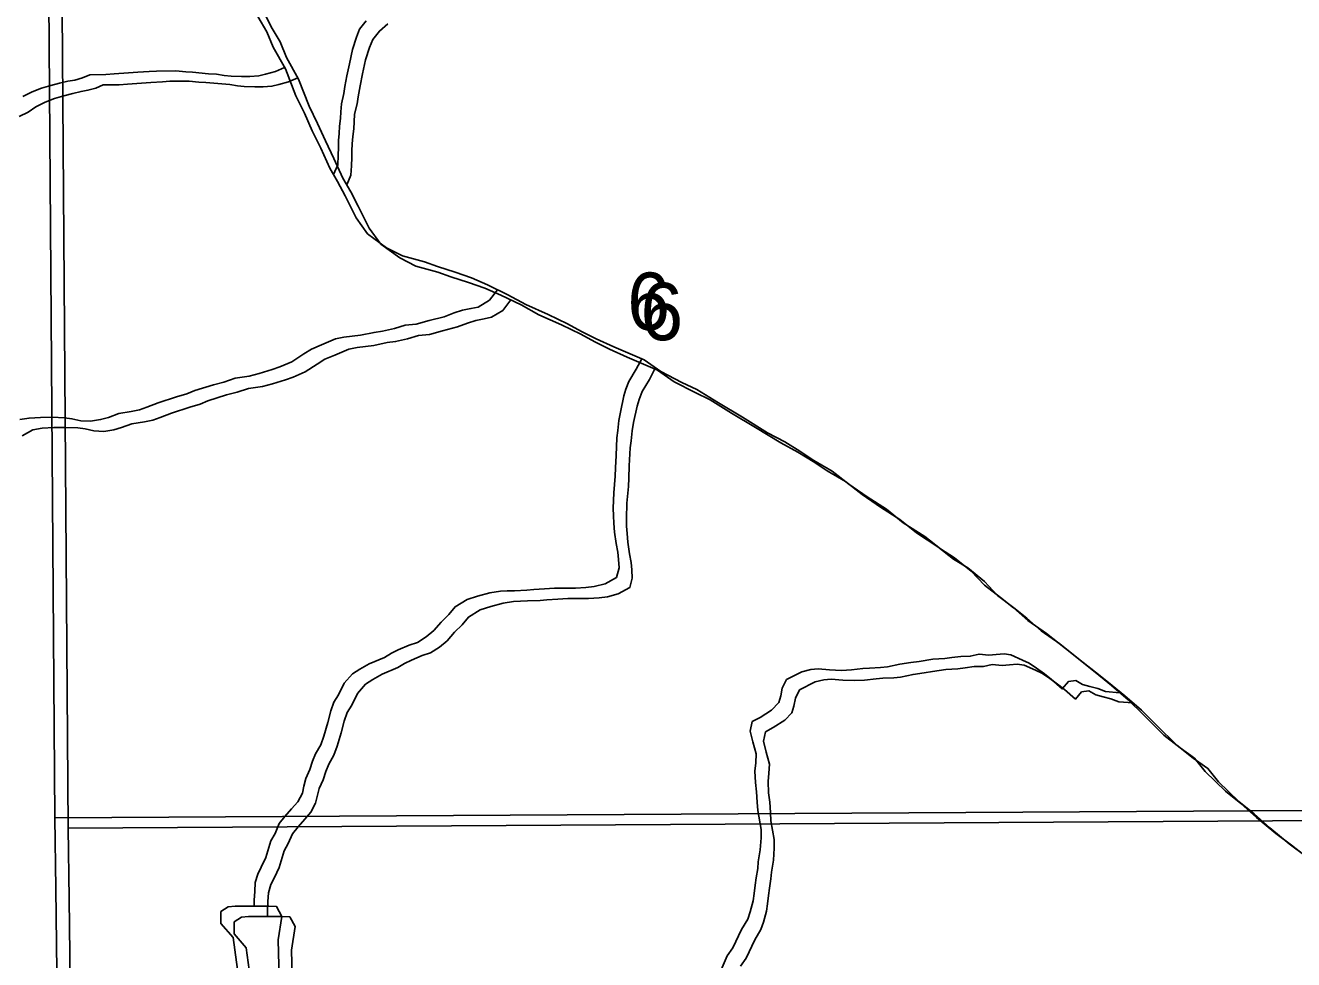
# Model space of a CAD drawing. Extents: x -21.1 to 50.3, y 0 to 22.1.
# Drawn here: x 44.072 to 44.997, y 18.617 to 19.298 of the extents above; entities that cross this region are included whole.
import ezdxf

# ---------------------------------------------------------------- set-up
doc = ezdxf.new("R2010")
doc.units = 0
for name, color, linetype in [('GM_X_Major_River', 7, 'Continuous'), ('GM_X_Minor_Lake', 7, 'Continuous'), ('GM_X_Minor_River', 7, 'Continuous'), ('GM_X_Section', 7, 'Continuous'), ('GM_X_Section_Text', 7, 'Continuous')]:
    doc.layers.add(name, color=color, linetype=linetype)

msp = doc.modelspace()

# ---------------------------------------------------------------- linework, layer by layer
at = {"layer": 'GM_X_Major_River'}
for points in [[(44.24162, 19.30473), (44.24815, 19.29377), (44.25278, 19.28242), (44.26162, 19.26654), (44.26934, 19.24685), (44.27549, 19.23437), (44.28128, 19.22151), (44.28744, 19.20865), (44.29398, 19.19427), (44.29974, 19.18444), (44.30513, 19.17385), (44.3132, 19.15797), (44.32163, 19.14626), (44.33535, 19.13611), (44.34716, 19.13012), (44.36312, 19.12569), (44.37262, 19.12234), (44.38555, 19.11826), (44.39733, 19.11417), (44.40913, 19.10894), (44.42397, 19.10184), (44.43691, 19.09472), (44.45327, 19.08725), (44.46735, 19.08052), (44.47763, 19.0749), (44.48829, 19.06966), (44.50123, 19.06369), (44.52329, 19.05436), (44.53549, 19.04572), (44.55071, 19.03786), (44.56175, 19.03262), (44.57737, 19.02287), (44.59489, 19.01237), (44.61317, 19.00112), (44.62573, 18.99437), (44.63678, 18.98762), (44.64707, 18.98086), (44.6604, 18.97299), (44.6726, 18.96359), (44.68594, 18.9542), (44.70004, 18.94519), (44.71224, 18.93541), (44.72787, 18.92527), (44.73931, 18.91625), (44.74959, 18.90987), (44.7618, 18.90009), (44.77135, 18.88991), (44.78317, 18.88089), (44.7927, 18.87337), (44.80301, 18.86395), (44.81673, 18.85456), (44.83046, 18.84365), (44.84267, 18.83387), (44.8522, 18.82635), (44.86403, 18.81657), (44.87624, 18.80603), (44.88731, 18.7951), (44.90217, 18.78045)], [(44.24625, 19.30782), (44.25126, 19.29723), (44.25779, 19.28627), (44.26242, 19.27492), (44.27125, 19.25904), (44.27898, 19.23935), (44.28513, 19.22687), (44.29091, 19.21401), (44.29707, 19.20114), (44.30362, 19.18677), (44.30938, 19.17694), (44.31476, 19.16635), (44.32284, 19.15047), (44.33127, 19.13876), (44.34499, 19.12861), (44.35679, 19.12262), (44.37275, 19.11819), (44.38226, 19.11484), (44.39518, 19.11076), (44.40697, 19.10667), (44.41876, 19.10144), (44.4336, 19.09434), (44.44655, 19.08722), (44.46291, 19.07975), (44.47699, 19.07302), (44.48727, 19.0674), (44.49793, 19.06216), (44.51086, 19.05619), (44.53293, 19.04686), (44.54512, 19.03822), (44.56035, 19.03036), (44.57139, 19.02512), (44.587, 19.01537), (44.60453, 19.00487), (44.62281, 18.99361), (44.63537, 18.98687), (44.64642, 18.98012), (44.65671, 18.97336), (44.67003, 18.96549), (44.68224, 18.95609), (44.69558, 18.9467), (44.70968, 18.93769), (44.72188, 18.92791), (44.7375, 18.91777), (44.74894, 18.90875), (44.75923, 18.90237), (44.77143, 18.89259), (44.78099, 18.88241), (44.79281, 18.87339), (44.80234, 18.86586), (44.81265, 18.85645), (44.82637, 18.84706), (44.8401, 18.83615), (44.8523, 18.82637), (44.86184, 18.81885), (44.87367, 18.80907), (44.88588, 18.79853), (44.89695, 18.7876), (44.91181, 18.77295)], [(44.90217, 18.78045), (44.91401, 18.77106), (44.92469, 18.76355), (44.93236, 18.75375), (44.94728, 18.73945), (44.95835, 18.73043), (44.96981, 18.72028), (44.98395, 18.70863), (44.9954, 18.69999), (45.00648, 18.69135)], [(44.91181, 18.77295), (44.92364, 18.76356), (44.93433, 18.75605), (44.942, 18.74625), (44.95691, 18.73195), (44.96799, 18.72293), (44.97945, 18.71278), (44.99359, 18.70113), (45.00504, 18.69249)]]:
    msp.add_lwpolyline(points, dxfattribs=at)
at = {"layer": 'GM_X_Minor_Lake'}
for points in [[(44.21461, 18.65156), (44.21467, 18.64283), (44.22347, 18.63265), (44.22789, 18.60043), (44.2322, 18.58186), (44.23497, 18.56556), (44.24714, 18.56224), (44.26028, 18.57943), (44.25707, 18.60294), (44.25649, 18.63102), (44.25901, 18.64812), (44.25517, 18.6553), (44.24947, 18.65564)], [(44.24947, 18.65564), (44.23471, 18.65552), (44.2251, 18.65552), (44.22001, 18.65515), (44.21461, 18.65156)], [(44.22425, 18.64406), (44.22431, 18.63533), (44.23311, 18.62515), (44.23752, 18.59293), (44.24183, 18.57436), (44.24461, 18.55806), (44.25677, 18.55474), (44.26992, 18.57193), (44.26671, 18.59544), (44.26612, 18.62352), (44.26865, 18.64062), (44.2648, 18.6478), (44.25911, 18.64814)], [(44.25911, 18.64814), (44.24435, 18.64802), (44.23474, 18.64802), (44.22965, 18.64764), (44.22425, 18.64406)]]:
    msp.add_lwpolyline(points, dxfattribs=at)
at = {"layer": 'GM_X_Minor_River'}
for points in [[(44.29672, 19.18961), (44.2998, 19.19656), (44.30012, 19.20341), (44.30045, 19.20949), (44.3004, 19.21444), (44.30074, 19.21938), (44.30108, 19.22471), (44.30179, 19.23042), (44.30213, 19.23536), (44.30246, 19.24107), (44.3043, 19.24869), (44.30502, 19.25364), (44.30647, 19.26163), (44.3083, 19.2704), (44.31049, 19.28068), (44.31345, 19.28983), (44.31569, 19.29555), (44.32058, 19.30167)], [(44.30635, 19.18211), (44.30943, 19.18906), (44.30975, 19.19591), (44.31008, 19.20199), (44.31004, 19.20693), (44.31038, 19.21188), (44.31071, 19.21721), (44.31143, 19.22292), (44.31176, 19.22786), (44.3121, 19.23357), (44.31393, 19.24119), (44.31465, 19.24614), (44.3161, 19.25413), (44.31793, 19.26289), (44.32013, 19.27318), (44.32309, 19.28233), (44.32532, 19.28805), (44.33021, 19.29417), (44.33625, 19.29955)], [(44.26099, 19.26767), (44.25435, 19.26463), (44.24714, 19.26267), (44.24221, 19.26149), (44.23575, 19.26106), (44.22967, 19.26101), (44.22206, 19.26133), (44.21711, 19.26167), (44.2114, 19.26276), (44.20569, 19.2631), (44.1939, 19.26414), (44.18895, 19.26448), (44.18172, 19.26518), (44.16765, 19.26507), (44.16233, 19.26465), (44.15397, 19.2642), (44.14713, 19.26376), (44.13687, 19.26292), (44.13079, 19.26249), (44.11901, 19.26239), (44.1137, 19.26007), (44.10801, 19.2585), (44.10308, 19.2577), (44.097, 19.25613), (44.09056, 19.25455), (44.08373, 19.2526), (44.0769, 19.24988), (44.07009, 19.2464)], [(44.27062, 19.26017), (44.26399, 19.25713), (44.25678, 19.25517), (44.25185, 19.25399), (44.24539, 19.25356), (44.2393, 19.25351), (44.2317, 19.25383), (44.22675, 19.25417), (44.22103, 19.25526), (44.21533, 19.2556), (44.20353, 19.25664), (44.19859, 19.25698), (44.19136, 19.25768), (44.17729, 19.25757), (44.17197, 19.25714), (44.16361, 19.2567), (44.15677, 19.25626), (44.14651, 19.25542), (44.14043, 19.25499), (44.12864, 19.25489), (44.12334, 19.25257), (44.11765, 19.251), (44.11271, 19.2502), (44.10664, 19.24863), (44.10019, 19.24705), (44.09336, 19.2451), (44.08654, 19.24238), (44.07973, 19.2389), (44.07406, 19.23505), (44.06762, 19.23196)], [(44.41636, 19.10548), (44.41052, 19.09784), (44.4022, 19.09283), (44.39688, 19.09164), (44.39081, 19.09045), (44.38474, 19.0885), (44.37754, 19.08578), (44.36654, 19.08303), (44.35706, 19.08029), (44.34908, 19.07947), (44.34111, 19.07712), (44.33238, 19.07515), (44.32631, 19.07434), (44.31644, 19.07236), (44.30428, 19.07073), (44.29821, 19.06955), (44.28798, 19.06528), (44.28078, 19.06218), (44.27511, 19.05871), (44.26641, 19.05294), (44.2577, 19.04906), (44.25201, 19.04712), (44.24253, 19.04438), (44.23532, 19.04242), (44.22507, 19.04081), (44.21673, 19.03808), (44.20914, 19.03612), (44.19549, 19.03183), (44.1898, 19.0295), (44.18222, 19.02716), (44.16895, 19.02287), (44.1606, 19.01976), (44.1553, 19.01781), (44.14922, 19.01662), (44.14011, 19.01502), (44.13253, 19.0123), (44.12684, 19.01073), (44.11963, 19.00953), (44.1124, 19.00986), (44.10592, 19.01132), (44.10059, 19.01204), (44.09147, 19.01235), (44.0831, 19.01228), (44.07474, 19.01183), (44.06791, 19.01063)], [(44.426, 19.09798), (44.42016, 19.09033), (44.41183, 19.08532), (44.40652, 19.08414), (44.40045, 19.08295), (44.39438, 19.081), (44.38718, 19.07828), (44.37618, 19.07553), (44.36669, 19.07279), (44.35871, 19.07196), (44.35075, 19.06962), (44.34202, 19.06765), (44.33594, 19.06684), (44.32607, 19.06486), (44.31392, 19.06323), (44.30785, 19.06204), (44.29762, 19.05778), (44.29042, 19.05468), (44.28474, 19.05121), (44.27605, 19.04544), (44.26734, 19.04156), (44.26165, 19.03961), (44.25217, 19.03688), (44.24496, 19.03492), (44.2347, 19.03331), (44.22636, 19.03058), (44.21877, 19.02862), (44.20512, 19.02432), (44.19944, 19.022), (44.19185, 19.01965), (44.17858, 19.01536), (44.17024, 19.01225), (44.16493, 19.01031), (44.15886, 19.00912), (44.14975, 19.00752), (44.14217, 19.0048), (44.13648, 19.00323), (44.12926, 19.00203), (44.12204, 19.00236), (44.11556, 19.00382), (44.11023, 19.00454), (44.1011, 19.00485), (44.09274, 19.00478), (44.08438, 19.00433), (44.07754, 19.00313), (44.06959, 18.99889)], [(44.52148, 19.05512), (44.51741, 19.04737), (44.51216, 19.03859), (44.50993, 19.03286), (44.50845, 19.02791), (44.50589, 19.0161), (44.5048, 19.01001), (44.5041, 19.00278), (44.50339, 18.99745), (44.50274, 18.98451), (44.50243, 18.97539), (44.5021, 18.9693), (44.50107, 18.95712), (44.50078, 18.94609), (44.50083, 18.94039), (44.50125, 18.93507), (44.50169, 18.92861), (44.5029, 18.92025), (44.5041, 18.9138), (44.50452, 18.90848), (44.50495, 18.9024), (44.50311, 18.89554), (44.49478, 18.89091), (44.48681, 18.88894), (44.48074, 18.88813), (44.47314, 18.88769), (44.45793, 18.88757), (44.45071, 18.88713), (44.44273, 18.88668), (44.43779, 18.88626), (44.42867, 18.88581), (44.42334, 18.88577), (44.4184, 18.88534), (44.41081, 18.88414), (44.4017, 18.88179), (44.39412, 18.87944), (44.38542, 18.87405), (44.38091, 18.86831), (44.37525, 18.86294), (44.36998, 18.85681), (44.36431, 18.8522), (44.35788, 18.84797), (44.35182, 18.84602), (44.34386, 18.84253), (44.33894, 18.84021), (44.33402, 18.83713), (44.32265, 18.83247), (44.31584, 18.82861), (44.31055, 18.82515), (44.30452, 18.81825), (44.30041, 18.80985), (44.29703, 18.8045), (44.29481, 18.79802), (44.2926, 18.78964), (44.28964, 18.77973), (44.28741, 18.77325), (44.28367, 18.76675), (44.28143, 18.76141), (44.27958, 18.75531), (44.27659, 18.74882), (44.27512, 18.74311), (44.27402, 18.73815), (44.27065, 18.73166), (44.26613, 18.72668), (44.26124, 18.72094), (44.2571, 18.71596), (44.25412, 18.70871), (44.25112, 18.70337), (44.24742, 18.69117), (44.24406, 18.68391), (44.24144, 18.67895), (44.23959, 18.67285), (44.23927, 18.66638), (44.23894, 18.65992), (44.23886, 18.65555)], [(44.53111, 19.04762), (44.52705, 19.03987), (44.5218, 19.03108), (44.51957, 19.02536), (44.51809, 19.02041), (44.51553, 19.0086), (44.51444, 19.00251), (44.51374, 18.99528), (44.51302, 18.98995), (44.51237, 18.97701), (44.51207, 18.96789), (44.51174, 18.9618), (44.5107, 18.94962), (44.51042, 18.93859), (44.51046, 18.93289), (44.51089, 18.92757), (44.51133, 18.92111), (44.51254, 18.91275), (44.51373, 18.9063), (44.51416, 18.90098), (44.51459, 18.8949), (44.51275, 18.88804), (44.50442, 18.88341), (44.49645, 18.88144), (44.49038, 18.88063), (44.48278, 18.88019), (44.46757, 18.88007), (44.46035, 18.87963), (44.45236, 18.87918), (44.44743, 18.87876), (44.4383, 18.87831), (44.43298, 18.87826), (44.42804, 18.87784), (44.42045, 18.87664), (44.41134, 18.87429), (44.40375, 18.87194), (44.39506, 18.86655), (44.39054, 18.86081), (44.38489, 18.85544), (44.37961, 18.84931), (44.37395, 18.8447), (44.36752, 18.84047), (44.36145, 18.83852), (44.3535, 18.83503), (44.34857, 18.83271), (44.34366, 18.82963), (44.33229, 18.82497), (44.32548, 18.82111), (44.32018, 18.81765), (44.31416, 18.81075), (44.31005, 18.80235), (44.30667, 18.797), (44.30444, 18.79052), (44.30223, 18.78214), (44.29928, 18.77223), (44.29705, 18.76575), (44.2933, 18.75925), (44.29107, 18.75391), (44.28922, 18.74781), (44.28623, 18.74132), (44.28476, 18.73561), (44.28366, 18.73065), (44.28029, 18.72416), (44.27577, 18.71918), (44.27088, 18.71344), (44.26674, 18.70846), (44.26375, 18.70121), (44.26076, 18.69586), (44.25706, 18.68367), (44.2537, 18.67641), (44.25108, 18.67145), (44.24923, 18.66535), (44.2489, 18.65888), (44.24858, 18.65242), (44.24849, 18.64805)], [(44.87008, 18.81134), (44.85972, 18.81212), (44.85399, 18.81436), (44.84828, 18.81583), (44.84294, 18.81731), (44.83797, 18.82031), (44.83266, 18.81951), (44.82814, 18.81415), (44.82009, 18.82131), (44.81512, 18.82507), (44.80938, 18.8292), (44.80403, 18.83297), (44.79906, 18.83521), (44.79067, 18.83894), (44.78572, 18.83966), (44.78002, 18.83923), (44.7747, 18.83881), (44.76747, 18.83951), (44.76102, 18.83794), (44.75417, 18.83788), (44.74771, 18.83707), (44.7424, 18.83627), (44.73366, 18.83581), (44.72378, 18.83421), (44.71771, 18.8334), (44.70973, 18.8322), (44.70063, 18.83022), (44.69568, 18.8298), (44.6877, 18.82936), (44.68276, 18.82894), (44.67441, 18.82811), (44.66719, 18.82767), (44.65844, 18.82798), (44.65007, 18.82867), (44.64475, 18.82825), (44.6383, 18.82667), (44.62694, 18.82088), (44.62395, 18.81477), (44.62285, 18.80906), (44.62138, 18.8041), (44.6161, 18.79873), (44.60778, 18.79334), (44.6021, 18.79026), (44.60064, 18.7834), (44.60261, 18.77543), (44.60496, 18.7667), (44.60464, 18.76024), (44.60393, 18.75415), (44.60438, 18.74579), (44.6052, 18.73895), (44.60564, 18.73135), (44.60608, 18.72527), (44.60847, 18.7116), (44.60852, 18.70551), (44.60784, 18.69676), (44.60639, 18.688), (44.60605, 18.68306), (44.60497, 18.6762), (44.60425, 18.67087), (44.60355, 18.66479), (44.60283, 18.65946), (44.60062, 18.65145), (44.59876, 18.64611), (44.59426, 18.63847), (44.58791, 18.62511), (44.58378, 18.61937), (44.5793, 18.60907)], [(44.87972, 18.80384), (44.86935, 18.80462), (44.86363, 18.80686), (44.85791, 18.80833), (44.85258, 18.80981), (44.84761, 18.81281), (44.84229, 18.81201), (44.83778, 18.80665), (44.82973, 18.81381), (44.82475, 18.81757), (44.81902, 18.8217), (44.81366, 18.82546), (44.8087, 18.82771), (44.8003, 18.83144), (44.79535, 18.83216), (44.78965, 18.83173), (44.78433, 18.83131), (44.7771, 18.83201), (44.77065, 18.83044), (44.76381, 18.83038), (44.75735, 18.82957), (44.75203, 18.82876), (44.74329, 18.82831), (44.73342, 18.82671), (44.72735, 18.8259), (44.71937, 18.8247), (44.71026, 18.82272), (44.70532, 18.8223), (44.69734, 18.82186), (44.6924, 18.82143), (44.68404, 18.82061), (44.67682, 18.82017), (44.66807, 18.82048), (44.6597, 18.82117), (44.65438, 18.82075), (44.64793, 18.81917), (44.63658, 18.81338), (44.63358, 18.80727), (44.63249, 18.80156), (44.63101, 18.7966), (44.62574, 18.79123), (44.61742, 18.78584), (44.61174, 18.78275), (44.61028, 18.7759), (44.61225, 18.76793), (44.6146, 18.7592), (44.61427, 18.75274), (44.61357, 18.74664), (44.61402, 18.73829), (44.61483, 18.73145), (44.61528, 18.72385), (44.61571, 18.71776), (44.61811, 18.7041), (44.61816, 18.69801), (44.61747, 18.68926), (44.61603, 18.6805), (44.61569, 18.67556), (44.61461, 18.6687), (44.61389, 18.66337), (44.61318, 18.65729), (44.61247, 18.65196), (44.61025, 18.64395), (44.6084, 18.63861), (44.6039, 18.63097), (44.59755, 18.61761), (44.59341, 18.61187)]]:
    msp.add_lwpolyline(points, dxfattribs=at)
at = {"layer": 'GM_X_Section'}
for points in [[(44.08631, 19.71488), (45.12856, 19.71587), (45.13143, 18.72623), (44.0935, 18.71999)], [(44.09595, 19.70738), (45.1382, 19.70837), (45.14107, 18.71873), (44.10314, 18.71249)], [(44.0935, 18.71999), (45.13143, 18.72623), (45.14863, 17.70187), (44.10665, 17.68876), (44.1055, 17.74068), (44.09428, 18.66845)], [(44.10314, 18.71249), (45.14107, 18.71873), (45.15827, 17.69437), (44.11629, 17.68126), (44.11514, 17.73318), (44.10391, 18.66095)]]:
    msp.add_lwpolyline(points, close=True, dxfattribs=at)

# ---------------------------------------------------------------- texts
at = {"layer": 'GM_X_Section_Text'}
for p in [(44.51092, 19.0761), (44.52056, 19.0686)]:
    msp.add_text('6', height=0.04186, rotation=0.00001, dxfattribs=at).set_placement(p)

doc.saveas('drawing.dxf')
